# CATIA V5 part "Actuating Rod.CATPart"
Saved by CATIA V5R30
Part number: Actuating Rod
Bounding box of the stored display mesh (mm): x -17.5 to 17.5, y -11.818 to 195.322, z -21 to 21
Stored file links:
  D:\PROJECTS\CATIA V56R 2020\Resources\Parts File\c12_catia_v5_6r2020_prt\c12_catia_v5-6r2020 figr_12-26\Actuating Rod.CATPart
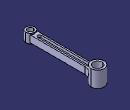
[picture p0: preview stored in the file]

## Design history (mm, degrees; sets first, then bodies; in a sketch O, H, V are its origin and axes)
Body1 (main body)
  Sketch1 on xy-plane, origin (0, 0, 0), H (1, 0, 0), V (0, 1, 0)
    arc A1 centre (0, 0) radius 12 from (-9, 7.9373) to (9, 7.9373) ccw
    arc A2 centre (0, 178) radius 17.5 from (13.5991, 166.9857) to (-13.5991, 166.9857) ccw
    point P1 (0, 178)
    line L1 (9, 154) -> (9, 7.9373)
    point P2 (9, 154)
    point P3 (9, 7.9373)
    arc A3 centre (29.6324, 154) radius 20.6324 from (9, 154) to (13.5991, 166.9857) cw
    point P5 (13.5991, 166.9857)
    point P6 (-13.5991, 166.9857)
    point P7 (-9, 154)
    arc A4 centre (-29.6324, 154) radius 20.6324 from (-9, 154) to (-13.5991, 166.9857) ccw
    point P9 (-9, 7.9373)
    line L2 (-9, 154) -> (-9, 7.9373)
    radius A2 = 17.5
    radius A1 = 12
    distance O P1 = 178
    distance V L1 = 9
    distance P1 P2 V = 24
    coincidence: P1 V
    vertical: L1 V
    tangency: A3 L1, A3 A2
    symmetry: P5 P6 V, P2 P7 V, A3 A4 V, P3 P9 V, L1 L2 V
  Pad1: profile Sketch1, direction (0, 0, 1), length 9, mirrored extent
  Sketch2 on xy-plane, origin (0, 0, 0), H (1, 0, 0), V (0, 1, 0)
    circle A1 centre (0, 0) radius 12
    reference projected arc E1 centre (0, 0) radius 12 from (-9, 7.9373) to (9, 7.9373) ccw from edge of Pad1
    reference projected arc E2 centre (0, 0) radius 12 from (-9, 7.9373) to (9, 7.9373) ccw from edge of Pad1
    reference projected arc E3 centre (0, 0) radius 12 from (-9, 7.9373) to (9, 7.9373) ccw from edge of Pad1
    concentricity: A1 E1, A1 E2
    tangency: A1 E3
  Pad2: profile Sketch2, direction (0, 0, 1), length 12, mirrored extent
  Sketch3 on xy-plane, origin (0, 0, 0), H (1, 0, 0), V (0, 1, 0)
    circle A1 centre (0, 178) radius 17.5
    point P1 (0, 178)
    reference projected arc E1 centre (0, 178) radius 17.5 from (13.5991, 166.9857) to (-13.5991, 166.9857) ccw from edge of Pad1
    reference projected arc E2 centre (0, 178) radius 17.5 from (13.5991, 166.9857) to (-13.5991, 166.9857) ccw from edge of Pad1
    coincidence: P1 V
    concentricity: A1 E1
    tangency: E2 A1
  Pad3: profile Sketch3, direction (0, 0, 1), length 21, mirrored extent
  Sketch4 on xy-plane, origin (0, 0, 0), H (1, 0, 0), V (0, 1, 0)
    circle A1 centre (0, 178) radius 12
    point P1 (0, 178)
    circle A2 centre (0, 0) radius 7.5
    reference projected circle E1 centre (0, 178) radius 17.5 from edge of Pad3
    radius A1 = 12
    radius A2 = 7.5
    coincidence: P1 V
    concentricity: A1 E1
  Pocket1: profile Sketch4, direction (0, 0, -1), length 21, mirrored extent
  Sketch5 on xy-plane, origin (0, 0, 0), H (1, 0, 0), V (0, 1, 0)
    construction line L1 (0, 24) -> (0, 154)
    point P1 (0, 24)
    line L2 (-5, 24) -> (-5, 154)
    line L3 (5, 154) -> (5, 24)
    arc A1 centre (0, 154) radius 5 from (-5, 154) to (5, 154) cw
    arc A2 centre (0, 24) radius 5 from (5, 24) to (-5, 24) cw
    length L1 = 130
    distance H P1 = 24
    radius A1 = 5
    coincidence: P1 V
    vertical: L1 V
    tangency: A1 L2, A2 L2, A1 L3, A2 L3
    parallelism: L1 L2
  Pocket2: profile Sketch5, direction (0, 0, -1), through (limit type 6), opposite side length -2.5
  Mirror1: of Pocket2, Sketch5, about xy-plane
